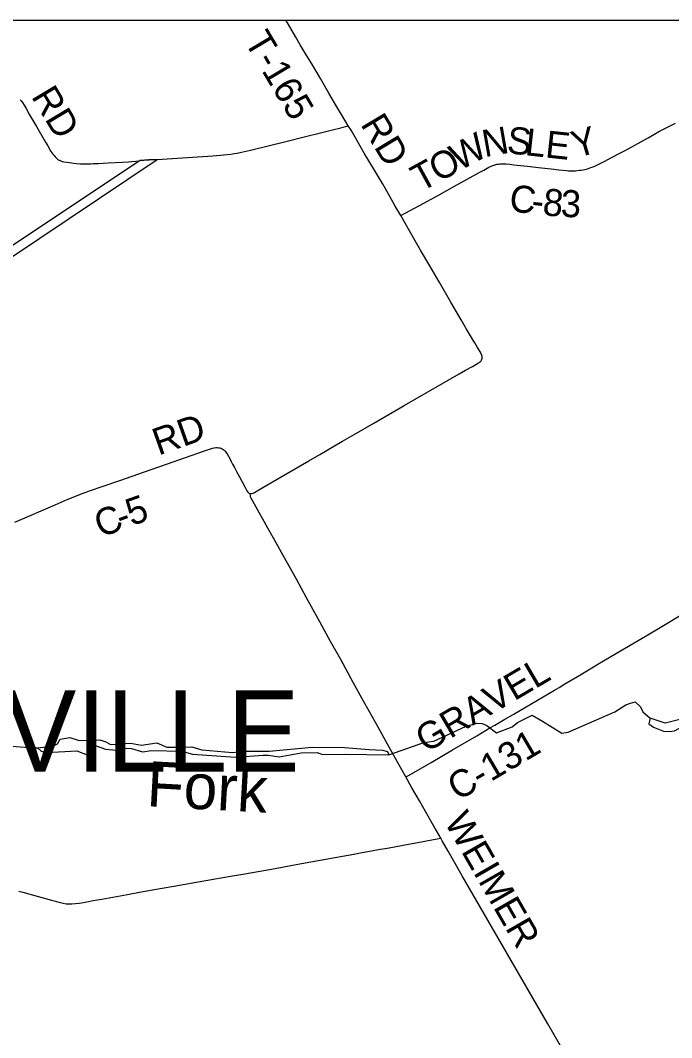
# Model space of a CAD drawing. Extents: x -49 to -8.2, y 9.4 to 23.5.
# Drawn here: x -13.469 to -12.785, y 15.141 to 16.209 of the extents above; entities that cross this region are included whole.
import ezdxf

# ---------------------------------------------------------------- set-up
doc = ezdxf.new("R2010")
doc.units = 0
for name, color, linetype in [('GM_X_Adjacent_County', 7, 'Continuous'), ('GM_X_Corporation', 7, 'Continuous'), ('GM_X_County_Road', 7, 'Continuous'), ('GM_X_County_Road_Text', 7, 'Continuous'), ('GM_X_Minor_River', 7, 'Continuous'), ('GM_X_Minor_River_Text', 7, 'Continuous'), ('GM_X_Township_Road', 7, 'Continuous'), ('GM_X_Township_Road_Text', 7, 'Continuous'), ('GM_X_Township_Text', 7, 'Continuous')]:
    doc.layers.add(name, color=color, linetype=linetype)

msp = doc.modelspace()

# ---------------------------------------------------------------- linework, layer by layer
at = {"layer": 'GM_X_Adjacent_County'}
msp.add_lwpolyline([(-14.9662, 16.2087), (-8.1662, 16.2087), (-8.1662, 9.4087), (-14.9662, 9.4087)], close=True, dxfattribs=at)
at = {"layer": 'GM_X_Corporation'}
msp.add_lwpolyline([(-14.0794, 15.5577), (-13.9715, 15.63), (-13.3251, 16.0625), (-13.334, 16.0623), (-13.343, 16.0616), (-13.9651, 15.6478), (-14.0519, 15.6841)], dxfattribs=at)
at = {"layer": 'GM_X_County_Road'}
for points in [[(-13.0695, 16.0038), (-13.0498, 16.0144), (-13.0291, 16.0256), (-13.013, 16.0345), (-12.9997, 16.0419), (-12.9864, 16.0493), (-12.9824, 16.0516), (-12.9788, 16.0535), (-12.9769, 16.0545), (-12.9752, 16.0553), (-12.9738, 16.056), (-12.9724, 16.0565), (-12.9715, 16.0568), (-12.9707, 16.0571), (-12.9697, 16.0574), (-12.9687, 16.0576), (-12.9677, 16.0578), (-12.9667, 16.0579), (-12.9655, 16.0581), (-12.9644, 16.0582), (-12.9628, 16.0582), (-12.9611, 16.0581), (-12.9588, 16.058), (-12.9551, 16.0577), (-12.9508, 16.0572), (-12.9369, 16.0556), (-12.9218, 16.0539), (-12.9116, 16.0528), (-12.9036, 16.0519), (-12.8956, 16.051), (-12.8933, 16.0509), (-12.8906, 16.0508), (-12.8883, 16.0508), (-12.8859, 16.0509), (-12.8839, 16.051), (-12.8816, 16.0513), (-12.8799, 16.0515), (-12.8779, 16.0519), (-12.8763, 16.0522), (-12.8749, 16.0526), (-12.8735, 16.053), (-12.8716, 16.0536), (-12.8697, 16.0542), (-12.8675, 16.055), (-12.8651, 16.0561), (-12.8627, 16.0572), (-12.856, 16.0605), (-12.8414, 16.0681), (-12.8338, 16.0722), (-12.8095, 16.0855), (-12.7976, 16.0922), (-12.7811, 16.1009)], [(-13.2277, 15.7121), (-13.2273, 15.712), (-13.2265, 15.712), (-13.2255, 15.7122), (-13.2245, 15.7126), (-13.2232, 15.7133), (-13.2213, 15.7144), (-13.2202, 15.7151), (-13.2184, 15.7161), (-13.21, 15.721), (-13.1952, 15.7295), (-13.1661, 15.7463), (-13.1543, 15.7532), (-13.1372, 15.7632), (-13.1305, 15.7671), (-13.1184, 15.7742), (-13.0979, 15.7858), (-13.0659, 15.8044), (-13.0543, 15.8111), (-13.0083, 15.8376), (-13.0015, 15.8414), (-12.9942, 15.8455), (-12.9888, 15.8485), (-12.9868, 15.8499), (-12.9859, 15.8506), (-12.9852, 15.8513), (-12.9846, 15.8522), (-12.9842, 15.853), (-12.984, 15.854), (-12.984, 15.8548), (-12.9841, 15.8559), (-12.9843, 15.857), (-12.985, 15.8586), (-12.9859, 15.8605), (-12.9889, 15.8653), (-12.9917, 15.8701), (-12.993, 15.8723), (-13.0003, 15.8846), (-13.0061, 15.8945), (-13.0169, 15.913), (-13.0292, 15.9342), (-13.0388, 15.9509), (-13.0486, 15.9675), (-13.0618, 15.9904), (-13.0695, 16.0038)], [(-13.4749, 15.6821), (-13.4324, 15.7004), (-13.4199, 15.7058), (-13.4031, 15.7126), (-13.3964, 15.715), (-13.382, 15.7199), (-13.3646, 15.7258), (-13.3385, 15.7349), (-13.3156, 15.7428), (-13.2755, 15.757), (-13.2725, 15.7581), (-13.2693, 15.7591), (-13.2671, 15.7598), (-13.2653, 15.7601), (-13.2637, 15.7603), (-13.2621, 15.7604), (-13.2607, 15.7602), (-13.2595, 15.76), (-13.2584, 15.7596), (-13.2571, 15.759), (-13.2559, 15.7583), (-13.2549, 15.7575), (-13.254, 15.7566), (-13.2531, 15.7555), (-13.2517, 15.7536), (-13.2487, 15.7481), (-13.2474, 15.7456), (-13.2461, 15.7431), (-13.244, 15.7393), (-13.242, 15.7354), (-13.2389, 15.7297), (-13.2332, 15.719), (-13.2322, 15.7171), (-13.231, 15.7149), (-13.2302, 15.7137), (-13.2295, 15.713), (-13.2288, 15.7126), (-13.2281, 15.7122), (-13.2277, 15.7121)], [(-13.0641, 15.4147), (-13.0606, 15.4166), (-13.0375, 15.4299), (-13.0152, 15.443), (-12.9897, 15.4579), (-12.9758, 15.4661), (-12.9708, 15.4691), (-12.9603, 15.4753), (-12.9514, 15.4804), (-12.9259, 15.4953), (-12.9081, 15.5059), (-12.9033, 15.5087), (-12.8971, 15.5124), (-12.8816, 15.5216), (-12.8606, 15.5342), (-12.8386, 15.5471), (-12.8201, 15.558), (-12.8118, 15.5629), (-12.7936, 15.5736), (-12.7733, 15.5857)], [(-13.4705, 15.295), (-13.4663, 15.2939), (-13.4514, 15.2896), (-13.4364, 15.2854), (-13.4334, 15.2846), (-13.4287, 15.2833), (-13.4241, 15.2822), (-13.421, 15.2817), (-13.419, 15.2815), (-13.4169, 15.2814), (-13.4149, 15.2815), (-13.407, 15.2823), (-13.4046, 15.2827), (-13.4009, 15.2833), (-13.3991, 15.2836), (-13.3924, 15.2849), (-13.3835, 15.2865), (-13.3563, 15.2915), (-13.3438, 15.2937), (-13.33, 15.2961), (-13.322, 15.2975), (-13.3055, 15.3005), (-13.2844, 15.3042), (-13.274, 15.306), (-13.2483, 15.3105), (-13.2333, 15.3131), (-13.2015, 15.3188), (-13.185, 15.3217), (-13.1697, 15.3245), (-13.148, 15.3285), (-13.1306, 15.3317), (-13.1187, 15.3338), (-13.1116, 15.335), (-13.093, 15.3384), (-13.0817, 15.3404), (-13.0612, 15.3441), (-13.0477, 15.3466), (-13.0425, 15.3476), (-13.0311, 15.3497), (-13.0275, 15.3503)]]:
    msp.add_lwpolyline(points, dxfattribs=at)
at = {"layer": 'GM_X_Minor_River'}
for points in [[(-13.0821, 15.4378), (-13.0451, 15.4508), (-13.0347, 15.4522), (-13.0008, 15.4679), (-12.9894, 15.471), (-12.9841, 15.4709), (-12.979, 15.4687), (-12.9689, 15.461), (-12.9526, 15.4674), (-12.947, 15.472), (-12.9316, 15.4794), (-12.9208, 15.4733), (-12.9004, 15.4608), (-12.8937, 15.4617), (-12.8446, 15.4831), (-12.8331, 15.4903), (-12.8281, 15.4923), (-12.8232, 15.4936), (-12.8177, 15.4882), (-12.8152, 15.4832), (-12.8077, 15.4763)], [(-12.6713, 15.496), (-12.6915, 15.4987), (-12.7225, 15.4956), (-12.7437, 15.4916), (-12.7511, 15.4887), (-12.7737, 15.4757), (-12.7918, 15.4713), (-12.8077, 15.4765), (-12.8091, 15.4706), (-12.8042, 15.4671), (-12.7937, 15.4629), (-12.7876, 15.4623), (-12.7821, 15.4631), (-12.749, 15.481), (-12.7187, 15.488), (-12.7031, 15.4894), (-12.6978, 15.4903), (-12.6714, 15.4864)], [(-13.7965, 15.4878), (-13.7843, 15.4849), (-13.7612, 15.4836), (-13.7175, 15.4776), (-13.7069, 15.4757), (-13.6767, 15.4745), (-13.6309, 15.4667), (-13.6018, 15.4615), (-13.5392, 15.4558), (-13.5176, 15.4541), (-13.4874, 15.4478), (-13.4547, 15.4452), (-13.451, 15.4453)], [(-13.451, 15.4453), (-13.4348, 15.4471), (-13.4298, 15.4493), (-13.4271, 15.4542), (-13.417, 15.4561), (-13.407, 15.4531), (-13.3855, 15.4537), (-13.3793, 15.4517), (-13.3742, 15.4486), (-13.3533, 15.4502), (-13.3418, 15.4479), (-13.3256, 15.4505), (-13.3151, 15.4458), (-13.2995, 15.4461), (-13.2887, 15.4463), (-13.2783, 15.4433), (-13.2463, 15.4403), (-13.2343, 15.4418), (-13.2127, 15.4417), (-13.2075, 15.4418), (-13.1625, 15.446), (-13.1285, 15.4457), (-13.1026, 15.4435), (-13.0888, 15.4429), (-13.0834, 15.4414), (-13.0821, 15.4378)], [(-13.451, 15.4453), (-13.4472, 15.4419), (-13.4414, 15.4404), (-13.4098, 15.4422), (-13.3989, 15.4378), (-13.3936, 15.4385), (-13.3944, 15.4432), (-13.3892, 15.4475), (-13.3794, 15.444), (-13.3679, 15.4428), (-13.3578, 15.4449), (-13.3521, 15.4447), (-13.3408, 15.4411), (-13.3311, 15.4424), (-13.2992, 15.4419), (-13.288, 15.4385), (-13.2431, 15.4353), (-13.2139, 15.4377), (-13.2085, 15.4376), (-13.197, 15.4359), (-13.174, 15.4401), (-13.1573, 15.4402), (-13.1518, 15.4384), (-13.1286, 15.4386), (-13.0821, 15.4378)]]:
    msp.add_lwpolyline(points, dxfattribs=at)
at = {"layer": 'GM_X_Township_Road'}
for points in [[(-13.1687, 16.1725), (-13.175, 16.1831), (-13.1797, 16.1911), (-13.1874, 16.2042), (-13.1901, 16.2087)], [(-13.1246, 16.0979), (-13.1318, 16.11), (-13.1355, 16.1162), (-13.145, 16.1322), (-13.1538, 16.1475), (-13.1619, 16.1612), (-13.1674, 16.1702), (-13.1687, 16.1725)], [(-13.4693, 16.1254), (-13.4682, 16.1241), (-13.4668, 16.1224), (-13.4651, 16.1198), (-13.4629, 16.1161), (-13.4592, 16.1096), (-13.452, 16.0973), (-13.4424, 16.0809), (-13.4401, 16.0769), (-13.4368, 16.0712), (-13.4348, 16.0681), (-13.4336, 16.0667), (-13.4325, 16.0653), (-13.431, 16.064), (-13.43, 16.0631), (-13.4289, 16.0624), (-13.4276, 16.0617), (-13.4263, 16.0612), (-13.4249, 16.0607), (-13.4232, 16.0603), (-13.4202, 16.0598), (-13.4174, 16.0594), (-13.4103, 16.0586), (-13.4056, 16.0581), (-13.4028, 16.058), (-13.3991, 16.058), (-13.3945, 16.0581), (-13.392, 16.0583), (-13.3873, 16.0585), (-13.3768, 16.0591), (-13.3616, 16.0598), (-13.3554, 16.0602), (-13.3517, 16.0605), (-13.3476, 16.061), (-13.3445, 16.0614)], [(-13.3251, 16.0625), (-13.2669, 16.0666), (-13.2479, 16.0683), (-13.2445, 16.0688), (-13.2411, 16.0694), (-13.2366, 16.0703), (-13.2272, 16.0724), (-13.1903, 16.0816), (-13.1695, 16.0866), (-13.1553, 16.0901), (-13.1411, 16.0936), (-13.1324, 16.0958), (-13.1276, 16.0971), (-13.1246, 16.0979)], [(-13.0695, 16.0038), (-13.0754, 16.0138), (-13.0813, 16.0244), (-13.0888, 16.0373), (-13.0969, 16.0513), (-13.1078, 16.0694), (-13.1175, 16.086), (-13.1217, 16.0933), (-13.1246, 16.0979)], [(-13.3445, 16.0614), (-13.3414, 16.0618), (-13.3391, 16.0621), (-13.3369, 16.0622), (-13.334, 16.0623)], [(-13.334, 16.0623), (-13.3338, 16.0622), (-13.3251, 16.0625)], [(-13.0641, 15.4147), (-13.0684, 15.4223), (-13.0751, 15.4342), (-13.0834, 15.4492), (-13.0932, 15.4668), (-13.1026, 15.4836), (-13.1085, 15.4942), (-13.1194, 15.5137), (-13.1325, 15.5381), (-13.1432, 15.557), (-13.1545, 15.5774), (-13.1683, 15.6028), (-13.179, 15.6221), (-13.1929, 15.6471), (-13.2003, 15.6604), (-13.2089, 15.6758), (-13.2129, 15.6829), (-13.2194, 15.6945), (-13.2267, 15.7073), (-13.227, 15.7079), (-13.2272, 15.7086), (-13.2273, 15.7094), (-13.2277, 15.7121)], [(-13.0275, 15.3503), (-13.0349, 15.3631), (-13.0436, 15.3785), (-13.0499, 15.3896), (-13.0577, 15.4033), (-13.0641, 15.4147)], [(-12.7975, 14.9524), (-12.8015, 14.9593), (-12.8161, 14.9846), (-12.8347, 15.0165), (-12.868, 15.074), (-12.9152, 15.1556), (-13.005, 15.3111), (-13.0197, 15.3367), (-13.026, 15.3478), (-13.0275, 15.3503)]]:
    msp.add_lwpolyline(points, dxfattribs=at)

# ---------------------------------------------------------------- texts
at = {"layer": 'GM_X_County_Road_Text'}
for s, height, rotation, p in [('W', 0.0284, 28.2901, (-13.0081, 16.0502)), ('N', 0.0284, 9.9396, (-12.9814, 16.065)), ('S', 0.0284, 354.1646, (-12.9588, 16.0693)), ('L', 0.0284, 353.6186, (-12.9398, 16.0673)), ('E', 0.0284, 353.9618, (-12.9185, 16.0649)), ('Y', 0.0284, 16.4437, (-12.8853, 16.0638)), ('O', 0.0284, 28.6826, (-13.03, 16.0382)), ('T', 0.0284, 28.6795, (-13.0486, 16.028)), ('C', 0.0284, 353.4995, (-12.9564, 16.0084)), ('8', 0.0284, 354.0388, (-12.9213, 16.0044)), ('3', 0.0284, 357.9213, (-12.9018, 16.0025)), ('-', 0.0284, 353.6144, (-12.9331, 16.0058)), ('RD', 0.02841, 19.5223, (-13.3239, 15.7518)), ('5', 0.0284, 19.6552, (-13.3521, 15.6778)), ('C', 0.0284, 21.8553, (-13.3842, 15.6653)), ('-', 0.0284, 20.2024, (-13.3629, 15.6738)), ('GRAVEL', 0.02841, 30.4143, (-13.0431, 15.4395)), ('C-131', 0.02841, 30.4931, (-13.0095, 15.389))]:
    msp.add_text(s, height=height, rotation=rotation, dxfattribs=at).set_placement(p)
at = {"layer": 'GM_X_Minor_River_Text'}
msp.add_text('Fork', height=0.04735, rotation=356.8336, dxfattribs=at).set_placement((-13.337, 15.3841))
at = {"layer": 'GM_X_Township_Road_Text'}
for s, rotation, p in [('T-165', 300.775, (-13.2344, 16.1868)), ('RD', 300.9654, (-13.458, 16.1288)), ('RD', 300.968, (-13.1123, 16.0996)), ('WEIMER', 299.8921, (-13.0244, 15.3679))]:
    msp.add_text(s, height=0.02841, rotation=rotation, dxfattribs=at).set_placement(p)
at = {"layer": 'GM_X_Township_Text'}
msp.add_text('CEDARVILLE', height=0.08523, rotation=0, dxfattribs=at).set_placement((-13.8852, 15.4204))

doc.saveas('drawing.dxf')
